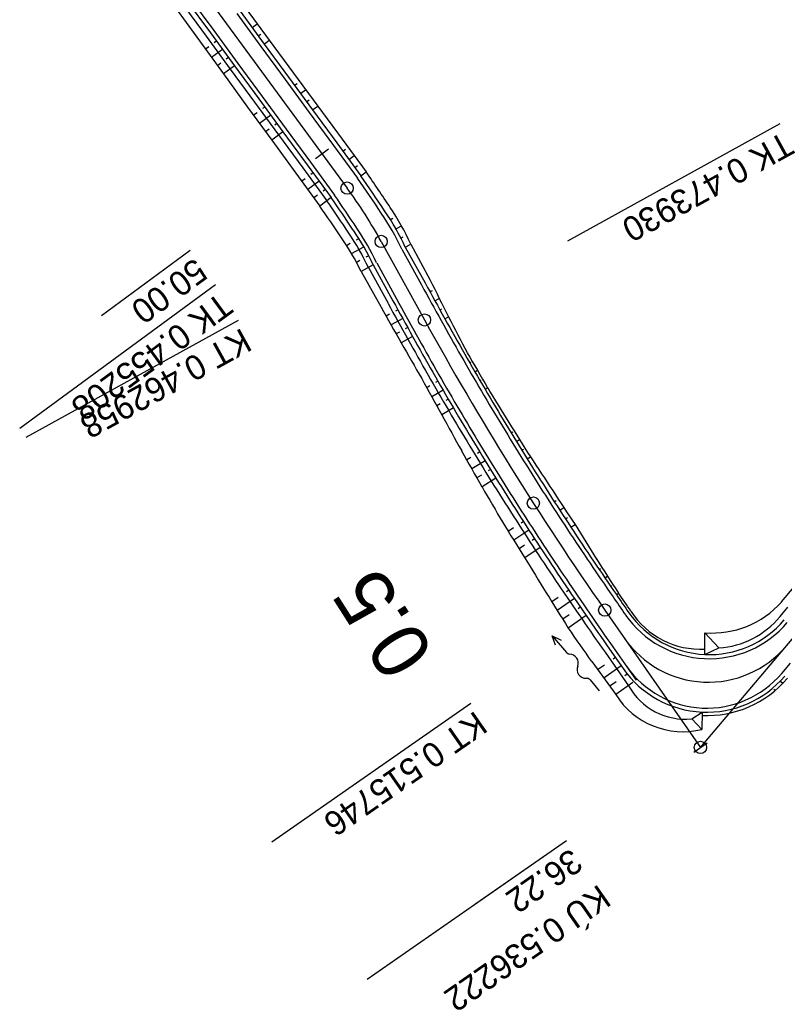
# Model space of a CAD drawing. Extents: x -481656 to -478728, y -1113199 to -1110710.
# Drawn here: x -480674.3 to -480580.8, y -1112993.4 to -1112872.3 of the extents above; entities that cross this region are included whole.
import ezdxf

# ---------------------------------------------------------------- set-up
doc = ezdxf.new("R2010")
doc.units = 0
for name, color, linetype in [('C13_HATCH_SLOPE_L', 7, 'Continuous'), ('C13_HATCH_SLOPE_R', 7, 'Continuous'), ('C13_HECTOMETRY', 7, 'Continuous'), ('C13_HLBODY', 7, 'Continuous'), ('C13_HRANA_TELESO', 7, 'Continuous'), ('C13_KORUNA', 7, 'Continuous'), ('C13_OSA', 7, 'Continuous'), ('C13_PRIKOP', 7, 'Continuous'), ('C13_STANICENI', 7, 'Continuous'), ('C13_VOZOVKA', 7, 'Continuous'), ('C13_ZPEVKRAJ', 7, 'Continuous'), ('C14_HATCH_SLOPE_R', 7, 'Continuous'), ('C14_HECTOMETRY', 7, 'Continuous'), ('C14_HLBODY', 7, 'Continuous'), ('C14_HRANA_TELESO', 7, 'Continuous'), ('C14_OSA', 7, 'Continuous'), ('C14_PRIKOP', 7, 'Continuous'), ('C14_ZPEVKRAJ', 7, 'Continuous'), ('DRENÁŽ', 7, 'Continuous'), ('křižovatky', 7, 'Continuous'), ('PLYN', 7, 'Continuous')]:
    doc.layers.add(name, color=color, linetype=linetype)

# ---------------------------------------------------------------- blocks, each defined once
blk = doc.blocks.new('A$C70B')
at = {"layer": 'DRENÁŽ'}
for p, q in [((0.87, 0), (-0.87, 0)), ((6.86, 0.43), (7.97, 0)), ((7.97, 0), (5.28, 0)), ((7.97, 0), (6.86, -0.48))]:
    blk.add_line(p, q, dxfattribs=at)
for centre, radius, start, end in [((0.87, 0.58), 0.582, 269.6924, 322.7901), ((2.17, -0.42), 1.05, 24.4039, 142.0836), ((4.08, 0.59), 1.11, 210.8873, 317.3707), ((5.32, -0.64), 0.636, 85.9766, 131.7248)]:
    blk.add_arc(centre, radius, start, end, dxfattribs=at)

msp = doc.modelspace()

# ---------------------------------------------------------------- linework, layer by layer
at = {"layer": 'C13_HATCH_SLOPE_L'}
for p, q in [((-480645.9, -1112873.22), (-480645.28, -1112872.76)), ((-480645.16, -1112874.22), (-480644.85, -1112874)), ((-480644.54, -1112873.77), (-480644.54, -1112873.77)), ((-480644.42, -1112875.23), (-480643.8, -1112874.77)), ((-480640.72, -1112880.27), (-480640.4, -1112880.04)), ((-480640.09, -1112879.8), (-480640.09, -1112879.8)), ((-480639.98, -1112881.28), (-480639.35, -1112880.81)), ((-480639.24, -1112882.28), (-480638.92, -1112882.05)), ((-480638.6, -1112881.82), (-480638.6, -1112881.82)), ((-480638.5, -1112883.29), (-480637.86, -1112882.82)), ((-480634.8, -1112888.33), (-480634.48, -1112888.09)), ((-480634.15, -1112887.85), (-480634.15, -1112887.85)), ((-480634.07, -1112889.34), (-480633.41, -1112888.86)), ((-480632.67, -1112889.86), (-480632.67, -1112889.86)), ((-480633.33, -1112890.34), (-480633, -1112890.1)), ((-480632.59, -1112891.35), (-480631.93, -1112890.87)), ((-480629.01, -1112896.75), (-480628.67, -1112896.55)), ((-480628.34, -1112896.35), (-480628.34, -1112896.35)), ((-480628.37, -1112897.88), (-480627.69, -1112897.5)), ((-480627.75, -1112898.99), (-480627.42, -1112898.8)), ((-480627.08, -1112898.61), (-480627.08, -1112898.61)), ((-480627.15, -1112900.08), (-480626.48, -1112899.71)), ((-480624.13, -1112905.55), (-480623.84, -1112905.39)), ((-480623.54, -1112905.23), (-480623.54, -1112905.23)), ((-480623.53, -1112906.65), (-480622.99, -1112906.35)), ((-480622.92, -1112907.74), (-480622.68, -1112907.61)), ((-480622.43, -1112907.47), (-480622.43, -1112907.47)), ((-480622.32, -1112908.83), (-480621.88, -1112908.59)), ((-480618.95, -1112914.06), (-480618.95, -1112914.06)), ((-480619.26, -1112914.24), (-480619.11, -1112914.15)), ((-480618.64, -1112915.32), (-480618.33, -1112915.13)), ((-480618.02, -1112916.39), (-480617.86, -1112916.3)), ((-480617.7, -1112916.21), (-480617.7, -1112916.21)), ((-480617.39, -1112917.46), (-480617.07, -1112917.28)), ((-480613.83, -1112922.57), (-480613.83, -1112922.57)), ((-480614.2, -1112922.79), (-480614.01, -1112922.68)), ((-480613.55, -1112923.85), (-480613.17, -1112923.63)), ((-480612.9, -1112924.91), (-480612.7, -1112924.79)), ((-480612.51, -1112924.68), (-480612.51, -1112924.68)), ((-480612.24, -1112925.97), (-480611.84, -1112925.72)), ((-480608.92, -1112931.22), (-480608.67, -1112931.06)), ((-480608.42, -1112930.91), (-480608.42, -1112930.91)), ((-480608.24, -1112932.26), (-480607.74, -1112931.94)), ((-480607.56, -1112933.31), (-480607.31, -1112933.14)), ((-480607.06, -1112932.98), (-480607.06, -1112932.98)), ((-480606.88, -1112934.35), (-480606.37, -1112934.01)), ((-480603.42, -1112939.51), (-480603.25, -1112939.39)), ((-480603.08, -1112939.28), (-480603.08, -1112939.28)), ((-480602.73, -1112940.54), (-480602.41, -1112940.32)), ((-480602.02, -1112941.56), (-480601.88, -1112941.46)), ((-480601.74, -1112941.37), (-480601.74, -1112941.37)), ((-480601.31, -1112942.58), (-480601.06, -1112942.41))]:
    msp.add_line(p, q, dxfattribs=at)
at = {"layer": 'C13_HATCH_SLOPE_R'}
for p, q in [((-480650.27, -1112874.87), (-480650.54, -1112875.07)), ((-480651.21, -1112875.56), (-480651.62, -1112875.86)), ((-480649.53, -1112875.88), (-480650.88, -1112876.87)), ((-480649.73, -1112877.58), (-480650.15, -1112877.88)), ((-480648.79, -1112876.89), (-480649.06, -1112877.08)), ((-480648.05, -1112877.89), (-480649.41, -1112878.89)), ((-480645.3, -1112883.63), (-480645.72, -1112883.94)), ((-480644.35, -1112882.93), (-480644.62, -1112883.13)), ((-480643.61, -1112883.94), (-480644.99, -1112884.95)), ((-480642.87, -1112884.95), (-480643.14, -1112885.14)), ((-480643.83, -1112885.65), (-480644.25, -1112885.96)), ((-480642.13, -1112885.95), (-480643.51, -1112886.97)), ((-480638.43, -1112890.99), (-480638.7, -1112891.19)), ((-480639.4, -1112891.7), (-480639.83, -1112892.02)), ((-480637.69, -1112892), (-480639.09, -1112893.03)), ((-480636.95, -1112893.01), (-480637.22, -1112893.21)), ((-480637.92, -1112893.72), (-480638.36, -1112894.04)), ((-480636.21, -1112894.02), (-480637.62, -1112895.05)), ((-480632.89, -1112899.04), (-480633.18, -1112899.21)), ((-480633.92, -1112899.64), (-480634.37, -1112899.91)), ((-480632.29, -1112900.08), (-480633.78, -1112900.91)), ((-480632.73, -1112901.73), (-480633.18, -1112901.98)), ((-480631.69, -1112901.16), (-480631.99, -1112901.32)), ((-480631.09, -1112902.25), (-480632.56, -1112903.06)), ((-480628.07, -1112907.73), (-480628.36, -1112907.89)), ((-480629.08, -1112908.28), (-480629.5, -1112908.51)), ((-480627.47, -1112908.82), (-480628.88, -1112909.6)), ((-480627.86, -1112910.46), (-480628.27, -1112910.69)), ((-480626.86, -1112909.91), (-480627.16, -1112910.07)), ((-480626.26, -1112911.01), (-480627.65, -1112911.79)), ((-480623.16, -1112916.49), (-480623.45, -1112916.65)), ((-480624.14, -1112917.04), (-480624.53, -1112917.27)), ((-480622.53, -1112917.57), (-480623.92, -1112918.38)), ((-480621.9, -1112918.66), (-480622.19, -1112918.83)), ((-480622.89, -1112919.24), (-480623.31, -1112919.48)), ((-480621.27, -1112919.74), (-480622.69, -1112920.58)), ((-480619.12, -1112925.8), (-480619.64, -1112926.11)), ((-480617.38, -1112926.21), (-480619.02, -1112927.21)), ((-480618.04, -1112925.14), (-480618.32, -1112925.31)), ((-480616.72, -1112927.28), (-480617.01, -1112927.45)), ((-480617.84, -1112927.97), (-480618.39, -1112928.31)), ((-480616.06, -1112928.35), (-480617.76, -1112929.41)), ((-480613.9, -1112934.43), (-480614.55, -1112934.85)), ((-480612.7, -1112933.66), (-480612.98, -1112933.84)), ((-480612.02, -1112934.71), (-480613.88, -1112935.93)), ((-480611.33, -1112935.77), (-480611.61, -1112935.95)), ((-480612.55, -1112936.56), (-480613.21, -1112937)), ((-480610.64, -1112936.82), (-480612.54, -1112938.07)), ((-480608.46, -1112942.94), (-480609.23, -1112943.46)), ((-480606.44, -1112943.08), (-480608.56, -1112944.53)), ((-480607.15, -1112942.04), (-480607.42, -1112942.23)), ((-480605.73, -1112944.12), (-480606, -1112944.31)), ((-480607.08, -1112945.05), (-480607.89, -1112945.61)), ((-480605.01, -1112945.15), (-480607.21, -1112946.68)), ((-480601.44, -1112950.28), (-480601.71, -1112950.47)), ((-480602.79, -1112951.23), (-480603.61, -1112951.79)), ((-480600.72, -1112951.31), (-480602.87, -1112952.8)), ((-480600.01, -1112952.33), (-480600.28, -1112952.52)), ((-480601.34, -1112953.26), (-480602.13, -1112953.81)), ((-480599.29, -1112953.36), (-480601.4, -1112954.82))]:
    msp.add_line(p, q, dxfattribs=at)
at = {"layer": 'C13_HECTOMETRY'}
msp.add_circle((-480611.48, -1112931.39), 0.75, dxfattribs=at)
at = {"layer": 'C13_HLBODY'}
for p, q in [((-480581.29, -1112884.98), (-480607.29, -1112899.33)), ((-480650.4, -1112904.69), (-480674.34, -1112922.26)), ((-480647.62, -1112909.04), (-480673.62, -1112923.38)), ((-480619.15, -1112955.91), (-480643.51, -1112972.89)), ((-480607.44, -1112972.71), (-480631.81, -1112989.69))]:
    msp.add_line(p, q, dxfattribs=at)
for centre in [(-480634.28, -1112892.85), (-480630.11, -1112899.38), (-480624.81, -1112908.99), (-480602.74, -1112944.48), (-480591.03, -1112961.28)]:
    msp.add_circle(centre, 0.75, dxfattribs=at)
at = {"layer": 'C13_HRANA_TELESO'}
for p, q in [((-480655.3, -1112870.81), (-480652.35, -1112874.85)), ((-480646.77, -1112870.75), (-480643.8, -1112874.77)), ((-480652.35, -1112874.85), (-480649.41, -1112878.89)), ((-480643.8, -1112874.77), (-480640.83, -1112878.8)), ((-480649.41, -1112878.89), (-480646.46, -1112882.93)), ((-480640.83, -1112878.8), (-480637.86, -1112882.82)), ((-480646.46, -1112882.93), (-480643.51, -1112886.97)), ((-480637.86, -1112882.82), (-480634.9, -1112886.85)), ((-480643.51, -1112886.97), (-480640.57, -1112891.01)), ((-480634.9, -1112886.85), (-480631.93, -1112890.87)), ((-480640.57, -1112891.01), (-480637.62, -1112895.05)), ((-480626.48, -1112899.71), (-480624.1, -1112904.1)), ((-480632.56, -1112903.06), (-480630.11, -1112907.42)), ((-480604.34, -1112950.78), (-480601.4, -1112954.82))]:
    msp.add_line(p, q, dxfattribs=at)
for centre, radius, start, end in [((-480787.47, -1112998.49), 189.14, 33.0917, 34.6799), ((-480775.06, -1112991.79), 168.07, 33.5443, 35.1399), ((-480655.13, -1112912.86), 31.52, 24.6601, 34.0294), ((-480657.89, -1112915.03), 28.01, 25.2754, 35.1138), ((-479554.4, -1112378.75), 1191.74, 206.15703, 206.39731), ((-479573.29, -1112315.01), 1211.54, 209.27317, 209.51012), ((-480269.1, -1112725.81), 397.32, 207.3887, 208.1052), ((-480276.26, -1112712.8), 403.82, 209.5225, 210.2388), ((-480274.92, -1112715.17), 397.39, 209.8541, 210.5703), ((-480270.51, -1112722.94), 403.85, 208.5849, 209.3012), ((-480276.16, -1112713.12), 397.36, 210.9152, 211.6315), ((-480267.66, -1112727.81), 403.99, 208.5011, 209.2177), ((-480277.16, -1112711.61), 397.31, 211.8922, 212.6085), ((-480267.45, -1112727.83), 404.17, 209.1997, 209.9163), ((-480279.02, -1112708.87), 397.23, 213.0863, 213.8026), ((-480267.36, -1112727.64), 404.34, 209.9347, 210.6513), ((-480276.12, -1112713.4), 397.16, 213.0273, 213.7435), ((-480270.28, -1112722.52), 404.48, 211.485, 212.2014), ((-480267.71, -1112726.43), 397.22, 211.5063, 212.2229), ((-480266.47, -1112728.42), 404.62, 211.2066, 211.9233), ((-480268.31, -1112725.2), 397.37, 212.4186, 213.1351), ((-480265.04, -1112730.35), 404.82, 211.5848, 212.3017), ((-480654, -1112980.47), 65.2, 33.3455, 35.7109), ((-480439.82, -1112832.78), 202.47, 214.2314, 215.649)]:
    msp.add_arc(centre, radius, start, end, dxfattribs=at)
at = {"layer": 'C13_KORUNA'}
for p, q in [((-480653.97, -1112869.83), (-480651.01, -1112873.86)), ((-480647.38, -1112871.2), (-480644.42, -1112875.23)), ((-480651.01, -1112873.86), (-480648.05, -1112877.89)), ((-480644.42, -1112875.23), (-480641.46, -1112879.26)), ((-480648.05, -1112877.89), (-480645.09, -1112881.92)), ((-480641.46, -1112879.26), (-480638.5, -1112883.29)), ((-480645.09, -1112881.92), (-480642.13, -1112885.95)), ((-480638.5, -1112883.29), (-480635.54, -1112887.32)), ((-480642.13, -1112885.95), (-480639.17, -1112889.99)), ((-480635.54, -1112887.32), (-480632.59, -1112891.35)), ((-480639.17, -1112889.99), (-480636.21, -1112894.02)), ((-480627.15, -1112900.08), (-480624.73, -1112904.46)), ((-480631.09, -1112902.25), (-480628.67, -1112906.63)), ((-480602.15, -1112949.26), (-480600.5, -1112951.63))]:
    msp.add_line(p, q, dxfattribs=at)
for centre, radius, start, end in [((-480785.79, -1112998.14), 186.75, 33.2888, 34.8776), ((-480778.33, -1112993.11), 173.25, 33.2932, 34.8869), ((-480655.35, -1112913.24), 31.12, 25.0179, 34.4356), ((-480657.29, -1112914.39), 28.88, 24.8453, 34.5569), ((-479578.83, -1112330.06), 1193.25, 208.77527, 209.01506), ((-479570.95, -1112325.71), 1206.75, 208.77647, 209.01415), ((-480274.55, -1112715.8), 397.75, 209.0321, 209.7483), ((-480274.55, -1112715.8), 402.25, 209.0321, 209.7483), ((-480274.55, -1112715.8), 397.75, 209.7483, 210.4645), ((-480274.55, -1112715.8), 402.25, 209.7483, 210.4645), ((-480274.55, -1112715.8), 397.75, 210.4645, 211.1807), ((-480274.55, -1112715.8), 402.25, 210.4645, 211.1807), ((-480274.55, -1112715.8), 397.75, 211.1807, 211.8969), ((-480274.55, -1112715.8), 402.25, 211.1807, 211.8969), ((-480274.55, -1112715.8), 397.75, 211.8969, 212.6131), ((-480274.55, -1112715.8), 402.25, 211.8969, 212.6131), ((-480274.55, -1112715.8), 397.75, 212.6131, 213.3293), ((-480274.55, -1112715.8), 402.25, 212.6131, 213.3293), ((-480274.55, -1112715.8), 397.75, 213.3293, 214.0455), ((-480274.55, -1112715.8), 402.25, 213.3293, 214.0455), ((-480274.55, -1112715.8), 397.75, 214.0455, 214.7617), ((-480274.55, -1112715.8), 402.25, 214.0455, 214.7617), ((-480436.71, -1112830.97), 198.88, 214.1408, 214.9166), ((-480438.56, -1112832.25), 201.12, 214.1476, 215.5732)]:
    msp.add_arc(centre, radius, start, end, dxfattribs=at)
at = {"layer": 'C13_OSA'}
for p, q in [((-480664.72, -1112851.37), (-480634.28, -1112892.85)), ((-480630.11, -1112899.38), (-480624.81, -1112908.99)), ((-480602.74, -1112944.48), (-480591.03, -1112961.28))]:
    msp.add_line(p, q, dxfattribs=at)
for centre, radius, start, end in [((-480682.64, -1112928.36), 60, 28.8789, 36.2792), ((-480274.55, -1112715.8), 400, 208.8788, 214.8684)]:
    msp.add_arc(centre, radius, start, end, dxfattribs=at)
at = {"layer": 'C13_PRIKOP'}
for p, q in [((-480654.5, -1112870.23), (-480651.54, -1112874.26)), ((-480651.54, -1112874.26), (-480648.59, -1112878.29)), ((-480648.59, -1112878.29), (-480645.63, -1112882.32)), ((-480645.63, -1112882.32), (-480642.67, -1112886.35)), ((-480642.67, -1112886.35), (-480639.71, -1112890.38)), ((-480639.71, -1112890.38), (-480636.75, -1112894.41)), ((-480631.67, -1112902.57), (-480629.26, -1112906.95)), ((-480602.7, -1112949.64), (-480599.84, -1112953.74))]:
    msp.add_line(p, q, dxfattribs=at)
for centre, radius, start, end in [((-480777.22, -1112992.36), 171.25, 33.2939, 34.8884), ((-480657.58, -1112914.55), 28.54, 24.8176, 34.5767), ((-479569.79, -1112325.07), 1208.75, 208.77664, 209.01402), ((-480274.55, -1112715.8), 402.92, 209.0321, 209.7483), ((-480274.55, -1112715.8), 402.92, 209.7483, 210.4645), ((-480274.55, -1112715.8), 402.92, 210.4645, 211.1807), ((-480274.55, -1112715.8), 402.92, 211.1807, 211.8969), ((-480274.55, -1112715.8), 402.92, 211.8969, 212.6131), ((-480274.55, -1112715.8), 402.92, 212.6131, 213.3293), ((-480274.55, -1112715.8), 402.92, 213.3293, 214.0455), ((-480274.55, -1112715.8), 402.92, 214.0455, 214.7617), ((-480438.83, -1112832.44), 201.46, 214.1486, 215.5722)]:
    msp.add_arc(centre, radius, start, end, dxfattribs=at)
at = {"layer": 'C13_STANICENI'}
for p, q in [((-480638.16, -1112889.25), (-480636.55, -1112888.06)), ((-480653.48, -1112900.49), (-480664.36, -1112908.48)), ((-480591.85, -1112961.85), (-480590.21, -1112960.71)), ((-480607.44, -1112972.71), (-480618.52, -1112980.43))]:
    msp.add_line(p, q, dxfattribs=at)
at = {"layer": 'C13_VOZOVKA'}
for p, q in [((-480653.56, -1112869.53), (-480650.6, -1112873.57)), ((-480647.78, -1112871.5), (-480644.82, -1112875.53)), ((-480650.6, -1112873.57), (-480647.64, -1112877.6)), ((-480644.82, -1112875.53), (-480641.86, -1112879.56)), ((-480647.64, -1112877.6), (-480644.69, -1112881.63)), ((-480641.86, -1112879.56), (-480638.91, -1112883.59)), ((-480644.69, -1112881.63), (-480641.73, -1112885.66)), ((-480638.91, -1112883.59), (-480635.95, -1112887.62)), ((-480641.73, -1112885.66), (-480638.77, -1112889.69)), ((-480635.95, -1112887.62), (-480632.99, -1112891.65)), ((-480638.77, -1112889.69), (-480635.81, -1112893.72)), ((-480627.59, -1112900.32), (-480625.17, -1112904.7)), ((-480630.65, -1112902.01), (-480628.24, -1112906.39)), ((-480601.74, -1112948.97), (-480598.88, -1112953.07))]:
    msp.add_line(p, q, dxfattribs=at)
for centre, radius, start, end in [((-480784.96, -1112997.58), 185.25, 33.2893, 34.8785), ((-480779.16, -1112993.67), 174.75, 33.2927, 34.8858), ((-480655.57, -1112913.37), 30.88, 24.9999, 34.4481), ((-480657.08, -1112914.26), 29.12, 24.8657, 34.5424), ((-479577.96, -1112329.57), 1194.75, 208.7754, 209.01496), ((-479571.83, -1112326.19), 1205.25, 208.77634, 209.01425), ((-480274.55, -1112715.8), 398.25, 209.0321, 209.7483), ((-480274.55, -1112715.8), 401.75, 209.0321, 209.7483), ((-480274.55, -1112715.8), 398.25, 209.7483, 210.4645), ((-480274.55, -1112715.8), 401.75, 209.7483, 210.4645), ((-480274.55, -1112715.8), 398.25, 210.4645, 211.1807), ((-480274.55, -1112715.8), 401.75, 210.4645, 211.1807), ((-480274.55, -1112715.8), 398.25, 211.1807, 211.8969), ((-480274.55, -1112715.8), 401.75, 211.1807, 211.8969), ((-480274.55, -1112715.8), 398.25, 211.8969, 212.6131), ((-480274.55, -1112715.8), 401.75, 211.8969, 212.6131), ((-480274.55, -1112715.8), 398.25, 212.6131, 213.3293), ((-480274.55, -1112715.8), 401.75, 212.6131, 213.3293), ((-480274.55, -1112715.8), 398.25, 213.3293, 214.0455), ((-480274.55, -1112715.8), 401.75, 213.3293, 214.0455), ((-480274.55, -1112715.8), 398.25, 214.0455, 214.7617), ((-480274.55, -1112715.8), 401.75, 214.0455, 214.7617), ((-480436.92, -1112831.11), 199.12, 214.1416, 214.9159), ((-480438.36, -1112832.11), 200.88, 214.1468, 215.574)]:
    msp.add_arc(centre, radius, start, end, dxfattribs=at)
at = {"layer": 'C13_ZPEVKRAJ'}
for p, q in [((-480653.56, -1112869.53), (-480650.6, -1112873.57)), ((-480647.78, -1112871.5), (-480644.82, -1112875.53)), ((-480650.6, -1112873.57), (-480647.64, -1112877.6)), ((-480644.82, -1112875.53), (-480641.86, -1112879.56)), ((-480647.64, -1112877.6), (-480644.69, -1112881.63)), ((-480641.86, -1112879.56), (-480638.91, -1112883.59)), ((-480644.69, -1112881.63), (-480641.73, -1112885.66)), ((-480638.91, -1112883.59), (-480635.95, -1112887.62)), ((-480641.73, -1112885.66), (-480638.77, -1112889.69)), ((-480635.95, -1112887.62), (-480632.99, -1112891.65)), ((-480638.77, -1112889.69), (-480635.81, -1112893.72)), ((-480627.59, -1112900.32), (-480625.17, -1112904.7)), ((-480630.65, -1112902.01), (-480628.24, -1112906.39)), ((-480601.74, -1112948.97), (-480598.88, -1112953.07))]:
    msp.add_line(p, q, dxfattribs=at)
for centre, radius, start, end in [((-480784.96, -1112997.58), 185.25, 33.2893, 34.8785), ((-480779.16, -1112993.67), 174.75, 33.2927, 34.8858), ((-480655.57, -1112913.37), 30.88, 24.9999, 34.4481), ((-480657.08, -1112914.26), 29.12, 24.8657, 34.5424), ((-479577.96, -1112329.57), 1194.75, 208.7754, 209.01496), ((-479571.83, -1112326.19), 1205.25, 208.77634, 209.01425), ((-480274.55, -1112715.8), 398.25, 209.0321, 209.7483), ((-480274.55, -1112715.8), 401.75, 209.0321, 209.7483), ((-480274.55, -1112715.8), 398.25, 209.7483, 210.4645), ((-480274.55, -1112715.8), 401.75, 209.7483, 210.4645), ((-480274.55, -1112715.8), 398.25, 210.4645, 211.1807), ((-480274.55, -1112715.8), 401.75, 210.4645, 211.1807), ((-480274.55, -1112715.8), 398.25, 211.1807, 211.8969), ((-480274.55, -1112715.8), 401.75, 211.1807, 211.8969), ((-480274.55, -1112715.8), 398.25, 211.8969, 212.6131), ((-480274.55, -1112715.8), 401.75, 211.8969, 212.6131), ((-480274.55, -1112715.8), 398.25, 212.6131, 213.3293), ((-480274.55, -1112715.8), 401.75, 212.6131, 213.3293), ((-480274.55, -1112715.8), 398.25, 213.3293, 214.0455), ((-480274.55, -1112715.8), 401.75, 213.3293, 214.0455), ((-480274.55, -1112715.8), 398.25, 214.0455, 214.7617), ((-480274.55, -1112715.8), 401.75, 214.0455, 214.7617), ((-480436.92, -1112831.11), 199.12, 214.1416, 214.9159), ((-480438.36, -1112832.11), 200.88, 214.1468, 215.574)]:
    msp.add_arc(centre, radius, start, end, dxfattribs=at)
at = {"layer": 'C14_HATCH_SLOPE_R'}
for p, q in [((-480581.23, -1112953.19), (-480580.92, -1112953.46)), ((-480582.04, -1112954.15), (-480581.89, -1112954.28)), ((-480581.73, -1112954.42), (-480581.73, -1112954.42))]:
    msp.add_line(p, q, dxfattribs=at)
at = {"layer": 'C14_HECTOMETRY'}
msp.add_circle((-480591.03, -1112961.28), 0.75, dxfattribs=at)
at = {"layer": 'C14_HLBODY'}
msp.add_circle((-480591.03, -1112961.28), 0.75, dxfattribs=at)
at = {"layer": 'C14_HRANA_TELESO'}
msp.add_line((-480581.09, -1112943.49), (-480577.89, -1112939.64), dxfattribs=at)
at = {"layer": 'C14_OSA'}
msp.add_line((-480591.03, -1112961.28), (-480529.75, -1112888.91), dxfattribs=at)
at = {"layer": 'C14_PRIKOP'}
msp.add_line((-480581.28, -1112945.25), (-480580.33, -1112944.13), dxfattribs=at)
at = {"layer": 'C14_ZPEVKRAJ'}
msp.add_line((-480581.08, -1112952.24), (-480580, -1112950.96), dxfattribs=at)
at = {"layer": 'křižovatky'}
for p, q in [((-480590.5, -1112949.92), (-480590.47, -1112947.25)), ((-480588.77, -1112949.11), (-480590.47, -1112947.25)), ((-480590.5, -1112949.92), (-480588.77, -1112949.11)), ((-480592.09, -1112957.8), (-480590.83, -1112956.97)), ((-480590.83, -1112956.97), (-480590.84, -1112959.08)), ((-480590.84, -1112959.08), (-480592.09, -1112957.8))]:
    msp.add_line(p, q, dxfattribs=at)
for centre, radius, start, end in [((-480589.58, -1112935.89), 11.4, 265.5343, 318.151), ((-480589.94, -1112937.91), 12.52, 214.9729, 319.6999), ((-480589.94, -1112937.91), 12.02, 214.9901, 319.698), ((-480591, -1112939.1), 10.17, 212.932, 273.0058), ((-480589.47, -1112938.55), 10.59, 273.8091, 320.6838), ((-480590.07, -1112940.8), 12.5, 214.8684, 319.744), ((-480590.24, -1112944.48), 12.5, 214.8684, 319.744), ((-480590.24, -1112944.48), 12, 214.8684, 319.744), ((-480590.24, -1112944.48), 12.91, 267.3062, 319.744), ((-480592.82, -1112949.79), 8.05, 209.4121, 275.245), ((-480593.17, -1112949.64), 9.72, 212.2087, 283.8922)]:
    msp.add_arc(centre, radius, start, end, dxfattribs=at)

# ---------------------------------------------------------------- block references
at = {"layer": 'PLYN', "rotation": 130.73036552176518}
msp.add_blockref('A$C70B', (-480603.97, -1112953.69), dxfattribs=at)

# ---------------------------------------------------------------- texts
at = {"layer": 'C13_HECTOMETRY'}
msp.add_text('0.5', height=6.999, rotation=122.5674, dxfattribs=at).set_placement((-480623.46, -1112949.79))
at = {"layer": 'C13_HLBODY'}
for s, rotation, p in [('TK 0.473930', 208.8789, (-480580.8, -1112885.86)), ('TK 0.455208', 216.2792, (-480649.81, -1112905.49)), ('KT 0.462958', 208.8789, (-480647.14, -1112909.91)), ('KT 0.515746', 214.8685, (-480618.57, -1112956.73)), ('KÚ 0.536222', 214.8685, (-480603.45, -1112977.95))]:
    msp.add_text(s, height=2.999, rotation=rotation, dxfattribs=at).set_placement(p)
at = {"layer": 'C13_STANICENI'}
for s, rotation, p in [('50.00', 216.2792, (-480652.89, -1112901.29)), ('36.22', 214.8685, (-480606.87, -1112973.53))]:
    msp.add_text(s, height=3, rotation=rotation, dxfattribs=at).set_placement(p)

doc.saveas('drawing.dxf')
